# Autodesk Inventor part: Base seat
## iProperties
Created: 2006-10
Part Number: Base seat
Document SubType Name: Modeling
Designer: John Croya
Density: 1 g/cm^3
Control State: 0
Master: False
Checked Out: False
Shininess: 64.0
Angle Display Precision: 2
Document Length Units: 11272
Document Angle Units: 11279
Document Time Units: 11290
Document Mass Units: 11286
Document Length Units Precision: 3
Document Angle Units Precision: 2
Compacted: False
Density: 0.0
Volumn: 0.0
Area: 0.0
PropertySet Name: Model Information
Author: John Croya
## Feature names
1. Revolution1
2. Revolution2
3. Extrusion1
